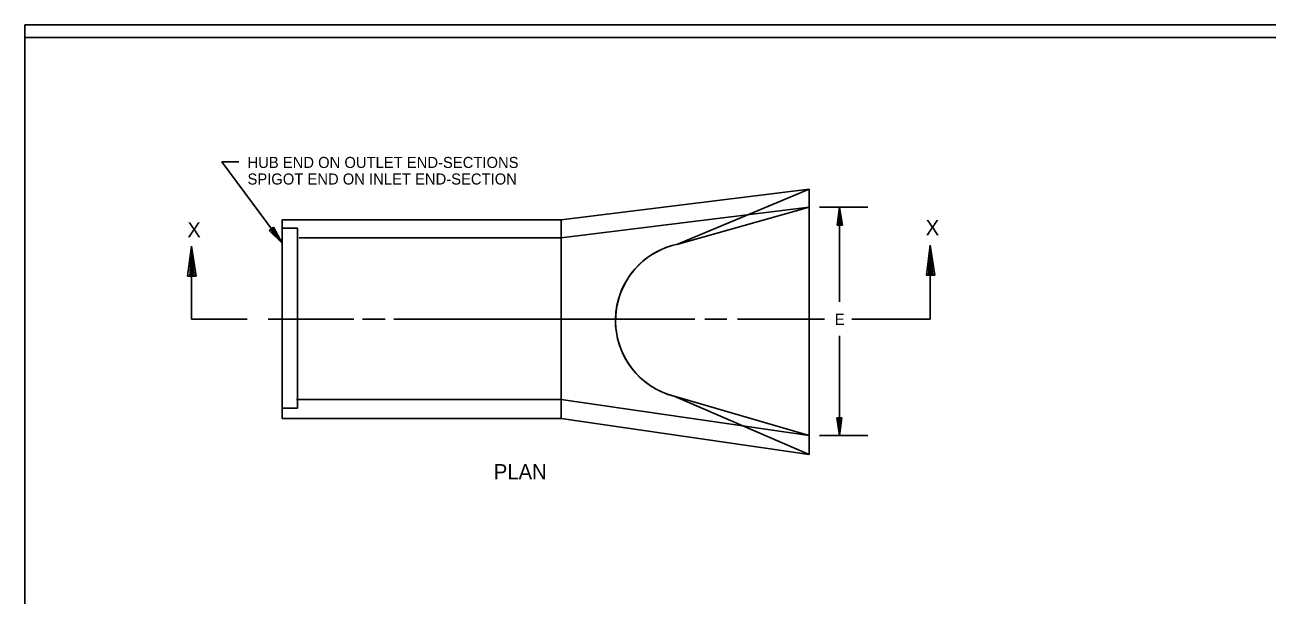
# Model space of a CAD drawing. Extents: x 0 to 390, y 0 to 265.
# Drawn here: x 0 to 245.7, y 152.2 to 265 of the extents above; entities that cross this region are included whole.
import ezdxf

# ---------------------------------------------------------------- set-up
doc = ezdxf.new("R2010")
doc.units = 0
doc.layers.add('D_Details', color=7, linetype='Continuous')
doc.layers.add('Default', color=7, linetype='Continuous')

msp = doc.modelspace()

# ---------------------------------------------------------------- linework, layer by layer
at = {"layer": 'D_Details'}
for p, q in [((42.32, 237.89), (38.95, 237.89)), ((38.95, 237.89), (50.93, 221.85)), ((106.12, 226.47), (155.14, 232.49)), ((155.14, 232.49), (128.96, 221.57)), ((155.14, 232.49), (155.14, 180.03)), ((106.12, 222.91), (155.14, 228.93)), ((155.14, 228.93), (128.96, 221.57)), ((157.2, 228.93), (166.74, 228.93)), ((161.16, 228.93), (160.7, 225.39)), ((161.72, 225.39), (161.16, 228.93)), ((161.16, 228.93), (161.16, 210.26)), ((50.93, 226.47), (50.93, 187.14)), ((50.93, 226.47), (106.12, 226.47)), ((106.12, 226.47), (106.12, 187.14)), ((160.96, 225.39), (161.16, 228.04)), ((161.08, 225.39), (161.18, 226.65)), ((161.16, 228.04), (161.46, 225.39)), ((161.18, 226.65), (161.34, 225.39)), ((49.17, 224.96), (48.36, 224.35)), ((48.36, 224.35), (50.93, 221.85)), ((50.4, 222.56), (48.56, 224.5)), ((49.54, 223.66), (48.66, 224.58)), ((48.87, 224.73), (49.54, 223.66)), ((48.97, 224.81), (50.4, 222.56)), ((50.93, 221.85), (49.17, 224.96)), ((50.93, 224.78), (53.92, 224.78)), ((53.92, 224.78), (53.92, 189.2)), ((160.7, 225.39), (161.72, 225.39)), ((32.96, 221.22), (32.2, 215.32)), ((32.96, 206.81), (32.96, 221.22)), ((33.89, 215.32), (32.96, 221.22)), ((54.29, 222.91), (106.12, 222.91)), ((179.09, 221.41), (178.33, 215.51)), ((179.09, 206.81), (179.09, 221.41)), ((180.02, 215.51), (179.09, 221.41)), ((32.63, 215.32), (32.96, 219.75)), ((32.96, 219.75), (33.47, 215.32)), ((178.76, 215.51), (179.09, 219.93)), ((179.09, 219.93), (179.6, 215.51)), ((32.84, 215.32), (33.01, 217.43)), ((33.01, 217.43), (33.26, 215.32)), ((178.97, 215.51), (179.14, 217.61)), ((179.14, 217.61), (179.39, 215.51)), ((32.2, 215.32), (33.89, 215.32)), ((178.33, 215.51), (180.02, 215.51)), ((44, 206.81), (32.96, 206.81)), ((48.12, 206.81), (65.07, 206.81)), ((66.82, 206.81), (71.25, 206.81)), ((73, 206.81), (132.55, 206.81)), ((134.54, 206.81), (138.85, 206.81)), ((140.97, 206.81), (158.17, 206.81)), ((163.59, 206.81), (179.09, 206.81)), ((161.16, 203.49), (161.16, 183.77)), ((53.73, 190.89), (106.12, 190.89)), ((106.12, 190.89), (155.14, 183.77)), ((155.14, 180.03), (128.43, 191.55)), ((155.14, 183.77), (128.43, 191.55)), ((53.92, 189.2), (50.93, 189.2)), ((50.93, 187.14), (106.12, 187.14)), ((106.12, 187.14), (155.14, 180.03)), ((161.61, 187.31), (160.6, 187.31)), ((160.6, 187.31), (161.16, 183.77)), ((161.16, 184.66), (160.86, 187.31)), ((161.13, 186.05), (160.98, 187.31)), ((161.23, 187.31), (161.13, 186.05)), ((161.16, 183.77), (161.61, 187.31)), ((161.36, 187.31), (161.16, 184.66)), ((157.2, 183.77), (166.74, 183.77))]:
    msp.add_line(p, q, dxfattribs=at)
for start in [101.9907, 105.8996]:
    msp.add_arc((132.29, 206.51), 15.45, start, 255.5304, dxfattribs=at)
at = {"layer": 'Default'}
for points in [[(0, 265), (326.25, 265), (326.25, 255), (390, 255), (390, 37.5), (315, 37.5), (315, 0), (0, 0)], [(0, 262.5), (326.25, 262.5), (326.25, 252.5), (390, 252.5), (390, 40), (315, 40), (315, 2.5), (0, 2.5)]]:
    msp.add_lwpolyline(points, close=True, dxfattribs=at)

# ---------------------------------------------------------------- texts
at = {"layer": 'D_Details'}
for s, height, p in [('HUB END ON OUTLET END-SECTIONS', 2.1869, (44.04, 236.7)), ('SPIGOT END ON INLET END-SECTION', 2.1869, (44.04, 233.42)), ('X', 3, (178.2, 223.39)), ('X', 3, (32.14, 222.98)), ('E', 2.19, (160.21, 205.67)), ('PLAN', 2.999, (92.76, 175.13))]:
    msp.add_text(s, height=height, dxfattribs=at).set_placement(p)

doc.saveas('drawing.dxf')
